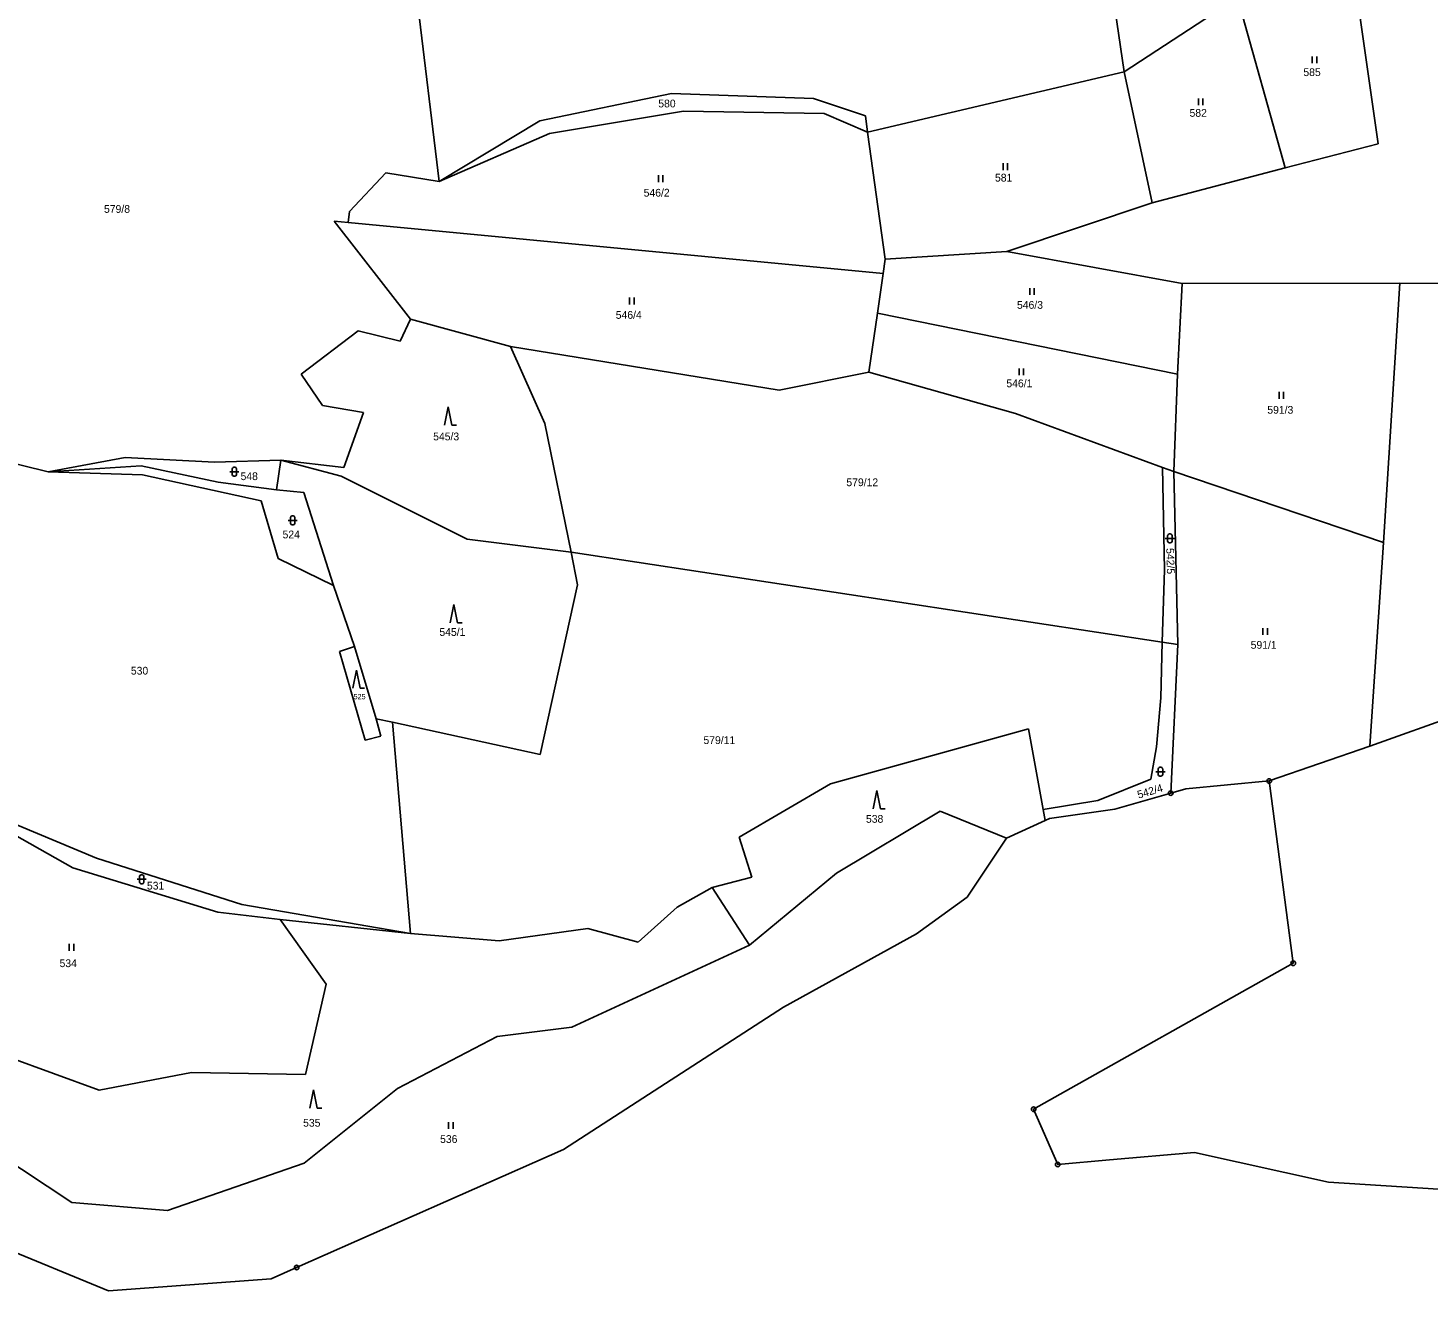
# Model space of a CAD drawing. Extents: x -794421 to -792735, y -1117671 to -1115559.
# Drawn here: x -793650.8 to -793344.4, y -1117521.2 to -1117244.8 of the extents above; entities that cross this region are included whole.
import ezdxf

# ---------------------------------------------------------------- set-up
doc = ezdxf.new("R2010")
doc.units = 0
for name, color, linetype in [('Vrstva 1', 7, 'Continuous'), ('Vrstva 14', 7, 'Continuous'), ('Vrstva 23', 7, 'Continuous'), ('Vrstva 28', 7, 'Continuous'), ('Vrstva 4', 7, 'Continuous')]:
    doc.layers.add(name, color=color, linetype=linetype)

msp = doc.modelspace()

# ---------------------------------------------------------------- linework, layer by layer
at = {"layer": 'Vrstva 1'}
for p, q in [((-793410.91, -1117254.36), (-793424.39, -1117162.26)), ((-793560.83, -1117278.35), (-793569.41, -1117207.36)), ((-793355.3, -1117270.13), (-793361.44, -1117226.97)), ((-793410.91, -1117254.36), (-793386.06, -1117238.09)), ((-793386.06, -1117238.09), (-793375.69, -1117275.37)), ((-793467.05, -1117267.58), (-793410.91, -1117254.36)), ((-793410.91, -1117254.36), (-793404.74, -1117283.03)), ((-793538.8, -1117265.06), (-793509.93, -1117259.11)), ((-793509.93, -1117259.11), (-793478.87, -1117260.17)), ((-793478.87, -1117260.17), (-793467.49, -1117263.97)), ((-793536.66, -1117267.83), (-793507.37, -1117262.96)), ((-793507.37, -1117262.96), (-793476.58, -1117263.47)), ((-793476.58, -1117263.47), (-793467.05, -1117267.58)), ((-793467.49, -1117263.97), (-793467.05, -1117267.58)), ((-793560.83, -1117278.35), (-793538.8, -1117265.06)), ((-793560.83, -1117278.35), (-793536.66, -1117267.83)), ((-793463.22, -1117295.34), (-793467.05, -1117267.58)), ((-793375.69, -1117275.37), (-793355.3, -1117270.13)), ((-793580.41, -1117284.92), (-793572.49, -1117276.43)), ((-793572.49, -1117276.43), (-793560.83, -1117278.35)), ((-793375.69, -1117275.37), (-793404.74, -1117283.03)), ((-793404.74, -1117283.03), (-793436.59, -1117293.64)), ((-793580.71, -1117287.31), (-793580.41, -1117284.92)), ((-793583.79, -1117287.01), (-793580.71, -1117287.31)), ((-793567.08, -1117308.51), (-793583.79, -1117287.01)), ((-793580.71, -1117287.31), (-793463.66, -1117298.46)), ((-793463.66, -1117298.46), (-793463.22, -1117295.34)), ((-793436.59, -1117293.64), (-793463.22, -1117295.34)), ((-793436.59, -1117293.64), (-793398.19, -1117300.65)), ((-793464.9, -1117307.17), (-793463.66, -1117298.46)), ((-793398.19, -1117300.65), (-793399.2, -1117320.55)), ((-793398.19, -1117300.65), (-793350.56, -1117300.6)), ((-793350.56, -1117300.6), (-793354.15, -1117357.33)), ((-793350.56, -1117300.6), (-793316.4, -1117300.84)), ((-793464.9, -1117307.17), (-793466.75, -1117320.11)), ((-793399.2, -1117320.55), (-793464.9, -1117307.17)), ((-793569.37, -1117313.28), (-793567.08, -1117308.51)), ((-793567.08, -1117308.51), (-793545.19, -1117314.43)), ((-793591, -1117320.52), (-793578.55, -1117311.07)), ((-793578.55, -1117311.07), (-793569.37, -1117313.28)), ((-793545.19, -1117314.43), (-793537.68, -1117331.3)), ((-793545.19, -1117314.43), (-793486.4, -1117324.02)), ((-793486.4, -1117324.02), (-793466.75, -1117320.11)), ((-793466.75, -1117320.11), (-793434.65, -1117329.11)), ((-793586.32, -1117327.41), (-793591, -1117320.52)), ((-793399.2, -1117320.55), (-793400.01, -1117341.8)), ((-793577.39, -1117328.9), (-793586.32, -1117327.41)), ((-793581.64, -1117340.93), (-793577.39, -1117328.9)), ((-793434.65, -1117329.11), (-793402.53, -1117340.95)), ((-793537.68, -1117331.3), (-793531.93, -1117359.49)), ((-793679.29, -1117333.94), (-793646.35, -1117341.87)), ((-793646.35, -1117341.87), (-793629.53, -1117338.74)), ((-793646.35, -1117341.87), (-793626.03, -1117340.58)), ((-793629.53, -1117338.74), (-793609.97, -1117339.81)), ((-793626.03, -1117340.58), (-793609.19, -1117344.14)), ((-793609.97, -1117339.81), (-793595.43, -1117339.35)), ((-793595.43, -1117339.35), (-793596.42, -1117345.83)), ((-793582.26, -1117342.87), (-793595.43, -1117339.35)), ((-793595.43, -1117339.35), (-793581.64, -1117340.93)), ((-793402.53, -1117340.95), (-793400.01, -1117341.8)), ((-793402.53, -1117340.95), (-793402.1, -1117363.31)), ((-793625.72, -1117342.55), (-793646.35, -1117341.87)), ((-793599.77, -1117348.26), (-793625.72, -1117342.55)), ((-793609.19, -1117344.14), (-793596.42, -1117345.83)), ((-793554.69, -1117356.61), (-793582.26, -1117342.87)), ((-793400.01, -1117341.8), (-793399.13, -1117379.71)), ((-793400.01, -1117341.8), (-793354.15, -1117357.33)), ((-793596.42, -1117345.83), (-793590.4, -1117346.44)), ((-793590.4, -1117346.44), (-793583.96, -1117366.74)), ((-793596.06, -1117360.88), (-793599.77, -1117348.26)), ((-793531.93, -1117359.49), (-793554.69, -1117356.61)), ((-793531.93, -1117359.49), (-793530.54, -1117366.61)), ((-793531.93, -1117359.49), (-793402.55, -1117379.19)), ((-793357.1, -1117401.96), (-793354.15, -1117357.33)), ((-793583.96, -1117366.74), (-793596.06, -1117360.88)), ((-793402.1, -1117363.31), (-793402.55, -1117379.19)), ((-793579.36, -1117380.13), (-793583.96, -1117366.74)), ((-793530.54, -1117366.61), (-793538.67, -1117403.72)), ((-793582.63, -1117381.19), (-793579.36, -1117380.13)), ((-793577.01, -1117400.6), (-793582.63, -1117381.19)), ((-793579.36, -1117380.13), (-793574.59, -1117395.94)), ((-793402.55, -1117379.19), (-793402.9, -1117391.32)), ((-793402.55, -1117379.19), (-793399.13, -1117379.71)), ((-793399.13, -1117379.71), (-793400.71, -1117412.21)), ((-793357.1, -1117401.96), (-793305.2, -1117383.22)), ((-793402.9, -1117391.32), (-793403.8, -1117402.06)), ((-793574.59, -1117395.94), (-793573.54, -1117399.74)), ((-793571.02, -1117396.71), (-793574.59, -1117395.94)), ((-793567.1, -1117442.9), (-793571.02, -1117396.71)), ((-793538.67, -1117403.72), (-793571.02, -1117396.71)), ((-793573.54, -1117399.74), (-793577.01, -1117400.6)), ((-793431.81, -1117398.15), (-793475.16, -1117410.16)), ((-793428.61, -1117415.78), (-793431.81, -1117398.15)), ((-793403.8, -1117402.06), (-793405.03, -1117409.18)), ((-793379.14, -1117409.54), (-793357.1, -1117401.96)), ((-793475.16, -1117410.16), (-793495.12, -1117421.85)), ((-793416.64, -1117413.83), (-793405.03, -1117409.18)), ((-793669.75, -1117412.29), (-793635.79, -1117426.44)), ((-793640.97, -1117428.56), (-793669.75, -1117412.29)), ((-793416.64, -1117413.83), (-793428.61, -1117415.78)), ((-793473.86, -1117429.72), (-793451.16, -1117416.14)), ((-793451.16, -1117416.14), (-793436.65, -1117422.09)), ((-793428.61, -1117415.78), (-793428.22, -1117418.23)), ((-793495.12, -1117421.85), (-793492.37, -1117430.59)), ((-793635.79, -1117426.44), (-793604.01, -1117436.56)), ((-793609.27, -1117438.26), (-793640.97, -1117428.56)), ((-793492.92, -1117445.46), (-793473.86, -1117429.72)), ((-793508.71, -1117437.14), (-793501.05, -1117432.84)), ((-793492.37, -1117430.59), (-793501.05, -1117432.84)), ((-793501.05, -1117432.84), (-793492.92, -1117445.46)), ((-793595.59, -1117439.87), (-793609.27, -1117438.26)), ((-793604.01, -1117436.56), (-793567.1, -1117442.9)), ((-793517.26, -1117444.79), (-793508.71, -1117437.14)), ((-793585.54, -1117453.98), (-793595.59, -1117439.87)), ((-793567.1, -1117442.9), (-793595.59, -1117439.87)), ((-793547.64, -1117444.53), (-793528.29, -1117441.84)), ((-793528.29, -1117441.84), (-793517.26, -1117444.79)), ((-793567.1, -1117442.9), (-793547.64, -1117444.53)), ((-793492.92, -1117445.46), (-793531.76, -1117463.39)), ((-793590.06, -1117473.78), (-793585.54, -1117453.98)), ((-793531.76, -1117463.39), (-793548.08, -1117465.49)), ((-793548.08, -1117465.49), (-793569.9, -1117476.81)), ((-793655.22, -1117469.9), (-793635.22, -1117477.22)), ((-793635.22, -1117477.22), (-793615, -1117473.35)), ((-793615, -1117473.35), (-793590.06, -1117473.78)), ((-793569.9, -1117476.81), (-793590.34, -1117493.22)), ((-793641.21, -1117501.77), (-793672.21, -1117481.31)), ((-793590.34, -1117493.22), (-793620.26, -1117503.54)), ((-793620.26, -1117503.54), (-793641.21, -1117501.77))]:
    msp.add_line(p, q, dxfattribs=at)
at = {"layer": 'Vrstva 23'}
for p, q in [((-793369.75, -1117252.49), (-793369.75, -1117250.99)), ((-793368.75, -1117250.99), (-793368.75, -1117252.49)), ((-793394.66, -1117261.67), (-793394.66, -1117260.17)), ((-793393.66, -1117260.17), (-793393.66, -1117261.67)), ((-793512.84, -1117278.5), (-793512.84, -1117277)), ((-793511.84, -1117277), (-793511.84, -1117278.5)), ((-793437.41, -1117275.86), (-793437.41, -1117274.36)), ((-793436.41, -1117274.36), (-793436.41, -1117275.86)), ((-793431.57, -1117303.18), (-793431.57, -1117301.68)), ((-793430.57, -1117301.68), (-793430.57, -1117303.18)), ((-793519.16, -1117305.25), (-793519.16, -1117303.75)), ((-793518.16, -1117303.75), (-793518.16, -1117305.25)), ((-793433.9, -1117320.75), (-793433.9, -1117319.25)), ((-793432.9, -1117319.25), (-793432.9, -1117320.75)), ((-793377, -1117325.91), (-793377, -1117324.41)), ((-793376, -1117324.41), (-793376, -1117325.91)), ((-793559.63, -1117331.68), (-793558.83, -1117327.68)), ((-793558.83, -1117327.68), (-793558.03, -1117331.68)), ((-793558.03, -1117331.68), (-793557.03, -1117331.68)), ((-793606.12, -1117341.26), (-793606.02, -1117341.06)), ((-793606.12, -1117342.46), (-793606.12, -1117341.26)), ((-793606.02, -1117341.06), (-793605.92, -1117340.96)), ((-793605.92, -1117340.96), (-793605.72, -1117340.86)), ((-793605.72, -1117340.86), (-793605.52, -1117340.86)), ((-793605.52, -1117340.86), (-793605.32, -1117340.96)), ((-793605.32, -1117340.96), (-793605.22, -1117341.06)), ((-793605.22, -1117341.06), (-793605.12, -1117341.26)), ((-793605.12, -1117341.26), (-793605.12, -1117342.46)), ((-793606.62, -1117341.86), (-793604.62, -1117341.86)), ((-793606.02, -1117342.66), (-793606.12, -1117342.46)), ((-793605.92, -1117342.76), (-793606.02, -1117342.66)), ((-793605.72, -1117342.86), (-793605.92, -1117342.76)), ((-793605.52, -1117342.86), (-793605.72, -1117342.86)), ((-793605.32, -1117342.76), (-793605.52, -1117342.86)), ((-793605.22, -1117342.66), (-793605.32, -1117342.76)), ((-793605.12, -1117342.46), (-793605.22, -1117342.66)), ((-793593.87, -1117352.52), (-793591.87, -1117352.52)), ((-793593.37, -1117351.92), (-793593.27, -1117351.72)), ((-793593.37, -1117353.12), (-793593.37, -1117351.92)), ((-793593.27, -1117353.32), (-793593.37, -1117353.12)), ((-793593.27, -1117351.72), (-793593.17, -1117351.62)), ((-793593.17, -1117353.42), (-793593.27, -1117353.32)), ((-793593.17, -1117351.62), (-793592.97, -1117351.52)), ((-793592.97, -1117353.52), (-793593.17, -1117353.42)), ((-793592.97, -1117351.52), (-793592.77, -1117351.52)), ((-793592.77, -1117353.52), (-793592.97, -1117353.52)), ((-793592.77, -1117351.52), (-793592.57, -1117351.62)), ((-793592.57, -1117353.42), (-793592.77, -1117353.52)), ((-793592.57, -1117351.62), (-793592.47, -1117351.72)), ((-793592.47, -1117353.32), (-793592.57, -1117353.42)), ((-793592.47, -1117351.72), (-793592.37, -1117351.92)), ((-793592.37, -1117353.12), (-793592.47, -1117353.32)), ((-793592.37, -1117351.92), (-793592.37, -1117353.12)), ((-793401.9, -1117356.46), (-793399.9, -1117356.46)), ((-793401.4, -1117355.86), (-793401.3, -1117355.66)), ((-793401.4, -1117357.06), (-793401.4, -1117355.86)), ((-793401.3, -1117355.66), (-793401.2, -1117355.56)), ((-793401.2, -1117355.56), (-793401, -1117355.46)), ((-793401, -1117355.46), (-793400.8, -1117355.46)), ((-793400.8, -1117355.46), (-793400.6, -1117355.56)), ((-793400.6, -1117355.56), (-793400.5, -1117355.66)), ((-793400.5, -1117355.66), (-793400.4, -1117355.86)), ((-793400.4, -1117355.86), (-793400.4, -1117357.06)), ((-793401.3, -1117357.26), (-793401.4, -1117357.06)), ((-793401.2, -1117357.36), (-793401.3, -1117357.26)), ((-793401, -1117357.46), (-793401.2, -1117357.36)), ((-793400.8, -1117357.46), (-793401, -1117357.46)), ((-793400.6, -1117357.36), (-793400.8, -1117357.46)), ((-793400.5, -1117357.26), (-793400.6, -1117357.36)), ((-793400.4, -1117357.06), (-793400.5, -1117357.26)), ((-793558.37, -1117374.93), (-793557.57, -1117370.93)), ((-793557.57, -1117370.93), (-793556.77, -1117374.93)), ((-793556.77, -1117374.93), (-793555.77, -1117374.93)), ((-793380.54, -1117377.59), (-793380.54, -1117376.09)), ((-793379.54, -1117376.09), (-793379.54, -1117377.59)), ((-793579.71, -1117389.26), (-793578.91, -1117385.26)), ((-793578.91, -1117385.26), (-793578.11, -1117389.26)), ((-793578.11, -1117389.26), (-793577.11, -1117389.26)), ((-793403.96, -1117407.52), (-793401.96, -1117407.52)), ((-793403.46, -1117406.92), (-793403.36, -1117406.72)), ((-793403.46, -1117408.12), (-793403.46, -1117406.92)), ((-793403.36, -1117408.32), (-793403.46, -1117408.12)), ((-793403.36, -1117406.72), (-793403.26, -1117406.62)), ((-793403.26, -1117408.42), (-793403.36, -1117408.32)), ((-793403.26, -1117406.62), (-793403.06, -1117406.52)), ((-793403.06, -1117408.52), (-793403.26, -1117408.42)), ((-793403.06, -1117406.52), (-793402.86, -1117406.52)), ((-793402.86, -1117408.52), (-793403.06, -1117408.52)), ((-793402.86, -1117406.52), (-793402.66, -1117406.62)), ((-793402.66, -1117408.42), (-793402.86, -1117408.52)), ((-793402.66, -1117406.62), (-793402.56, -1117406.72)), ((-793402.56, -1117408.32), (-793402.66, -1117408.42)), ((-793402.56, -1117406.72), (-793402.46, -1117406.92)), ((-793402.46, -1117408.12), (-793402.56, -1117408.32)), ((-793402.46, -1117406.92), (-793402.46, -1117408.12)), ((-793465.81, -1117415.65), (-793465.01, -1117411.65)), ((-793465.01, -1117411.65), (-793464.21, -1117415.65)), ((-793464.21, -1117415.65), (-793463.21, -1117415.65)), ((-793626.4, -1117430.46), (-793626.3, -1117430.26)), ((-793626.3, -1117430.26), (-793626.2, -1117430.16)), ((-793626.2, -1117430.16), (-793626, -1117430.06)), ((-793626, -1117430.06), (-793625.8, -1117430.06)), ((-793625.8, -1117430.06), (-793625.6, -1117430.16)), ((-793625.6, -1117430.16), (-793625.5, -1117430.26)), ((-793625.5, -1117430.26), (-793625.4, -1117430.46)), ((-793626.9, -1117431.06), (-793624.9, -1117431.06)), ((-793626.4, -1117431.66), (-793626.4, -1117430.46)), ((-793626.3, -1117431.86), (-793626.4, -1117431.66)), ((-793626.2, -1117431.96), (-793626.3, -1117431.86)), ((-793626, -1117432.06), (-793626.2, -1117431.96)), ((-793625.8, -1117432.06), (-793626, -1117432.06)), ((-793625.6, -1117431.96), (-793625.8, -1117432.06)), ((-793625.5, -1117431.86), (-793625.6, -1117431.96)), ((-793625.4, -1117431.66), (-793625.5, -1117431.86)), ((-793625.4, -1117430.46), (-793625.4, -1117431.66)), ((-793641.78, -1117446.69), (-793641.78, -1117445.19)), ((-793640.78, -1117445.19), (-793640.78, -1117446.69)), ((-793589.11, -1117481.16), (-793588.31, -1117477.16)), ((-793588.31, -1117477.16), (-793587.51, -1117481.16)), ((-793587.51, -1117481.16), (-793586.51, -1117481.16)), ((-793558.77, -1117485.69), (-793558.77, -1117484.19)), ((-793557.77, -1117484.19), (-793557.77, -1117485.69))]:
    msp.add_line(p, q, dxfattribs=at)
at = {"layer": 'Vrstva 28'}
for centre, radius in [((-793400.71, -1117412.21), 0.5), ((-793379.14, -1117409.54), 0.5), ((-793379.14, -1117409.54), 0.01), ((-793400.71, -1117412.21), 0.01), ((-793373.89, -1117449.44), 0.5), ((-793373.89, -1117449.44), 0.01), ((-793430.71, -1117481.39), 0.5), ((-793430.71, -1117481.39), 0.01), ((-793425.44, -1117493.47), 0.5), ((-793425.44, -1117493.47), 0.01), ((-793591.99, -1117516.03), 0.5), ((-793591.99, -1117516.03), 0.01)]:
    msp.add_circle(centre, radius, dxfattribs=at)
at = {"layer": 'Vrstva 4'}
for p, q in [((-793400.71, -1117412.21), (-793397.43, -1117411.28)), ((-793397.43, -1117411.28), (-793379.14, -1117409.54)), ((-793379.14, -1117409.54), (-793373.89, -1117449.44)), ((-793412.91, -1117415.69), (-793400.71, -1117412.21)), ((-793428.22, -1117418.23), (-793427.25, -1117417.79)), ((-793427.25, -1117417.79), (-793412.91, -1117415.69)), ((-793436.65, -1117422.09), (-793428.22, -1117418.23)), ((-793445.25, -1117434.98), (-793436.65, -1117422.09)), ((-793456.32, -1117442.97), (-793445.25, -1117434.98)), ((-793485.46, -1117459.05), (-793456.32, -1117442.97)), ((-793373.89, -1117449.44), (-793430.71, -1117481.39)), ((-793533.57, -1117490.19), (-793485.46, -1117459.05)), ((-793430.71, -1117481.39), (-793425.44, -1117493.47)), ((-793591.99, -1117516.03), (-793533.57, -1117490.19)), ((-793414.09, -1117492.47), (-793395.48, -1117490.83)), ((-793395.48, -1117490.83), (-793366.2, -1117497.33)), ((-793425.44, -1117493.47), (-793414.09, -1117492.47)), ((-793366.2, -1117497.33), (-793324.32, -1117499.98)), ((-793659.95, -1117510.07), (-793633.17, -1117521.16)), ((-793597.58, -1117518.48), (-793591.99, -1117516.03)), ((-793633.17, -1117521.16), (-793597.58, -1117518.48))]:
    msp.add_line(p, q, dxfattribs=at)

# ---------------------------------------------------------------- texts
at = {"layer": 'Vrstva 14'}
for s, height, p in [('585', 1.7, (-793371.679, -1117255.28)), ('580', 1.7, (-793512.852, -1117262.14)), ('582', 1.7, (-793396.593, -1117264.19)), ('581', 1.7, (-793439.166, -1117278.37)), ('546/2', 1.7, (-793516.052, -1117281.66)), ('579/8', 1.7, (-793634.153, -1117285.21)), ('546/3', 1.7, (-793434.352, -1117306.21)), ('546/4', 1.7, (-793522.158, -1117308.4)), ('546/1', 1.7, (-793436.675, -1117323.38)), ('591/3', 1.7, (-793379.57, -1117329.17)), ('545/3', 1.7, (-793562.118, -1117335)), ('548', 1.7, (-793604.269, -1117343.7)), ('579/12', 1.7, (-793471.686, -1117345.03)), ('524', 1.7, (-793595.079, -1117356.45)), ('545/1', 1.7, (-793560.752, -1117377.8)), ('591/1', 1.7, (-793383.213, -1117380.61)), ('530', 1.7, (-793628.272, -1117386.26)), ('525', 1.14, (-793579.538, -1117391.65)), ('579/11', 1.7, (-793502.969, -1117401.46)), ('538', 1.7, (-793467.403, -1117418.69)), ('531', 1.7, (-793624.756, -1117433.31)), ('534', 1.7, (-793643.879, -1117450.28)), ('535', 1.7, (-793590.579, -1117485.2)), ('536', 1.7, (-793560.603, -1117488.76))]:
    msp.add_text(s, height=height, dxfattribs=at).set_placement(p)
for s, rotation, p in [('542/5', 271.73457, (-793401.696, -1117358.612)), ('542/4', 16.49016, (-793407.735, -1117413.417))]:
    msp.add_text(s, height=1.7, rotation=rotation, dxfattribs=at).set_placement(p)

doc.saveas('drawing.dxf')
